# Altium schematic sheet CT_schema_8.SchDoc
size 254 x 194 mm
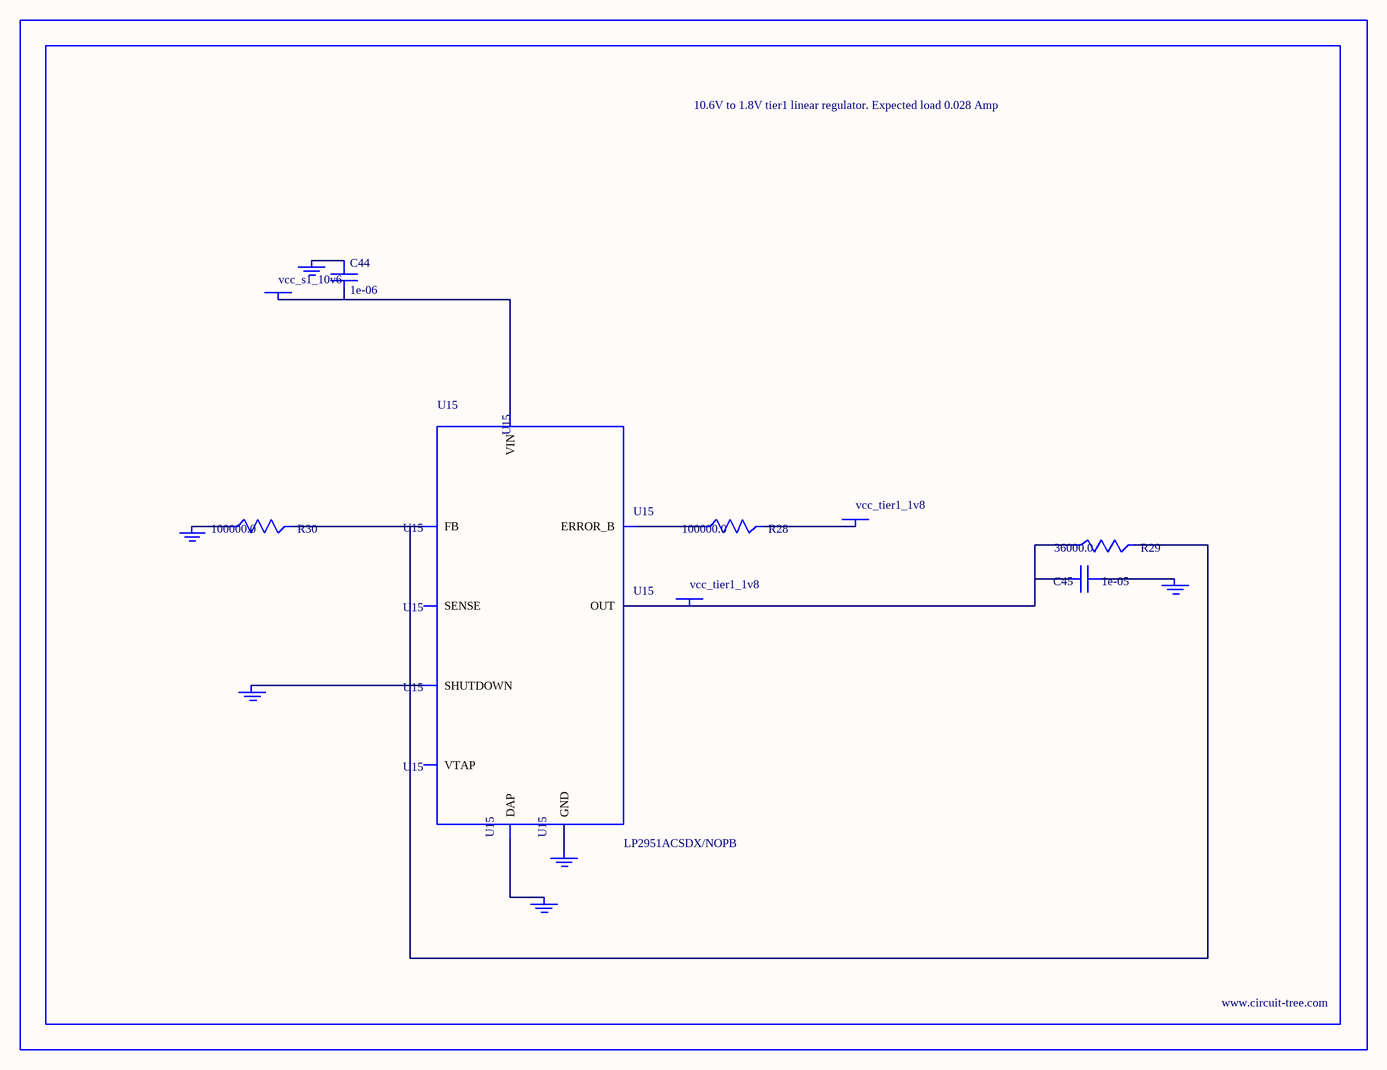
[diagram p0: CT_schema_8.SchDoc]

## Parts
BORDER7  (no value)
C44  1e-06  [C0603]
C45  1e-05  [C0805]
GND_INSTANCE_7_0  (no value)
GND_INSTANCE_7_1  (no value)
GND_INSTANCE_7_2  (no value)
GND_INSTANCE_7_3  (no value)
GND_INSTANCE_7_4  (no value)
GND_INSTANCE_7_5  (no value)
POWER_INSTANCE_7_0  vcc_tier1_1v8
POWER_INSTANCE_7_1  vcc_s1_10v6
POWER_INSTANCE_7_2  vcc_tier1_1v8
R28  100000.0  [R0603]
R29  36000.0  [R0603]
R30  100000.0  [R0603]
U15  LP2951ACSDX/NOPB  [WSON-8]

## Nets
NetC44_1: C44.1 GND_INSTANCE_7_3.0(GND)
NetC44_2: C44.2 POWER_INSTANCE_7_1.0(PWR) U15.8(VIN)
NetC45_1: C45.1 GND_INSTANCE_7_0.0(GND)
NetC45_2: C45.2 POWER_INSTANCE_7_2.0(PWR) R29.1 U15.1(OUT)
NetGND_INSTANCE_7_1_0: GND_INSTANCE_7_1.0(GND) U15.3(SHUTDOWN)
NetGND_INSTANCE_7_2_0: GND_INSTANCE_7_2.0(GND) R30.1
NetGND_INSTANCE_7_4_0: GND_INSTANCE_7_4.0(GND) U15.PAD(DAP)
NetGND_INSTANCE_7_5_0: GND_INSTANCE_7_5.0(GND) U15.4(GND)
NetPOWER_INSTANCE_7_0_0: POWER_INSTANCE_7_0.0(PWR) R28.2
NetR28_1: R28.1 U15.5(ERROR_B)
NetR29_2: R29.2 R30.2 U15.7(FB)

Not connected (* = marked no-connect by the designer): U15 2(SENSE) 6(VTAP)

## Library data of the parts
BORDER7 = BORDER_PAGE7
C44 = C0603C105K3RACTU
C45 = GRM219R60J106ME19D
GND_INSTANCE_7_0-GND_INSTANCE_7_5 = GND
POWER_INSTANCE_7_0-POWER_INSTANCE_7_2 = PWR
R28 R30 = RC0603JR-07100KL
R29 = RC0603JR-0736KL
